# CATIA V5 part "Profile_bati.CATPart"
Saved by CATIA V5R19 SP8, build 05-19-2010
Part number: Profile_bati
Bounding box of the stored display mesh (mm): x -253 to 253, y -52.5 to 72.5, z -226 to 100
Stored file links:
  G:\EU_thinkMotion\CFAO_2010\MMS_groupe1\MMS_groupe1\OK\vduret\vduret\CATIA\Profile_bati.CATPart
  G:\EU_thinkMotion\CFAO_2010\MMS_groupe1\MMS_groupe1\OK\vduret\vduret\CATIA\Axe_outil_g.CATPart
  F:\CFAO TP\Machine_de_coupe.CATProduct
  G:\EU_thinkMotion\CFAO_2010\MMS_groupe1\MMS_groupe1\OK\vduret\vduret\CATIA\Tige_sync.CATPart
  G:\EU_thinkMotion\CFAO_2010\MMS_groupe1\MMS_groupe1\OK\vduret\vduret\CATIA\Axe.CATPart
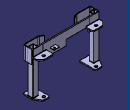
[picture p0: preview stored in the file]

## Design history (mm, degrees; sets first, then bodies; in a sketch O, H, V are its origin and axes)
Parameters
  Largeur_bati = 500 mm
  Hauteur_bati = 70 mm
External parameters (linked from other documents)
  External.Longueur_axe_couronne = 200 mm
Body1 (main body)
  Sketch1 on xy-plane, origin (0, 0, 0), H (1, 0, 0), V (0, 1, 0)
    line L1 (-250, 17.5) -> (-175, 17.5)
    line L2 (-210, 9.5) -> (-210, -17.5)
    line L3 (-210, -17.5) -> (-250, -17.5)
    line L4 (-250, 11.5) -> (-250, 17.5)
    line L5 (-246, 13.5) -> (-214, 13.5)
    line L6 (-214, 13.5) -> (-214, -13.5)
    line L7 (-214, -13.5) -> (-246, -13.5)
    line L8 (-246, -13.5) -> (-246, 13.5)
    line L9 (175, 17.5) -> (250, 17.5)
    line L10 (250, -21.5) -> (210, -21.5)
    line L11 (250, 17.5) -> (250, 11.5)
    line L12 (210, -21.5) -> (210, 9.5)
    line L13 (214, 13.5) -> (246, 13.5)
    line L14 (246, -17.5) -> (214, -17.5)
    line L15 (246, 13.5) -> (246, -17.5)
    line L16 (214, -17.5) -> (214, 13.5)
    point P9 (0, 0)
    line L17 (-175, 17.5) -> (175, 17.5)
    line L18 (210, 9.5) -> (-210, 9.5)
    line L19 (-253, 11.5) -> (-250, 11.5)
    line L20 (-250, -17.5) -> (-250, -48.5)
    line L21 (-253, -38.5) -> (-253, 11.5)
    line L22 (250, 11.5) -> (253, 11.5)
    line L23 (253, 11.5) -> (253, -36.5)
    line L24 (250, -48.5) -> (250, -21.5)
    line L25 (-250, -48.5) -> (-144.0718, -48.5)
    line L26 (-143, -52.5) -> (-253, -52.5)
    line L27 (-253, -52.5) -> (-253, -38.5)
    point P33 (253, -52.5)
    line L28 (253, -52.5) -> (143, -52.5)
    line L29 (144.0718, -48.5) -> (250, -48.5)
    line L30 (253, -36.5) -> (253, -52.5)
    point P35 (144.0718, -48.5)
    line L31 (-144.0718, -48.5) -> (-113.7609, -31)
    line L32 (-143, -52.5) -> (-111.7609, -34.4641)
    point P38 (-111.7609, -34.4641)
    line L33 (144.0718, -48.5) -> (113.7609, -31)
    line L34 (143, -52.5) -> (111.7609, -34.4641)
    line L35 (113.7609, -31) -> (111.7609, -34.4641)
    line L36 (-113.7609, -31) -> (-111.7609, -34.4641)
    point P41 (-111.7609, -34.4641)
    point P42 (-198, -52.5)
    distance L5 L1 = 4
    distance L6 L2 = 4
    distance L7 L3 = 4
    distance L8 L4 = 4
    distance L13 L9 = 4
    distance L15 L11 = 4
    distance L14 L10 = 4
    distance L16 L12 = 4
    distance L4 V = 250 {= Largeur_bati /2}
    distance V L11 = 250 {= Largeur_bati /2}
    distance L1 H = 17.5
    distance L9 H = 17.5
    distance L9 L14 = 35
    distance L17 L18 = 8
    length L19 = 3
    distance L19 L1 = 6
    distance L22 L9 = 6
    length L26 = 110
    length L28 = 110
    length L33 = 35
    length L31 = 35
    angle L34 L28 = 30
    angle L32 L26 = 30
    distance L25 L26 = 4
    distance L31 L32 = 4
    distance L1 L3 = 35
    distance L4 L2 = 40
    distance L33 L34 = 4
    distance L28 L29 = 4
    distance L23 L24 = 3
    distance L12 L11 = 40
    distance L17 L26 = 70 {= Hauteur_bati}
    horizontal: L1 H, L3 H, L5 H, L7 H, L10 H, L9 H, L17 H, L18 H, L19 H, L22 H, L25 H, L26 H, L28 H, L29 H
    vertical: L2 V, L4 V, L6 V, L8 V, L16 V, L12 V, L20 V, L21 V, L23 V, L24 V, L27 V, L30 V
    coincidence: L17 L1, L20 L4, L24 L11, P33 L23, P35 L25, P41 L32, L36 P38
    perpendicularity: L35 L33, L31 L36
    midpoint: P42 L26
  Pad1: profile Sketch1, direction (0, 0, 1), length 100
  Sketch2 on start face of Pad1, origin (0, 0, 0), H (1, 0, 0), V (0, -1, 0)
    line L1 (-250, 17.5) -> (-210, 17.5)
    line L2 (-210, 17.5) -> (-210, -17.5)
    line L3 (-210, -17.5) -> (-250, -17.5)
    line L4 (-250, -17.5) -> (-250, 17.5)
    line L5 (-246, 13.5) -> (-214, 13.5)
    line L6 (-214, 13.5) -> (-214, -13.5)
    line L7 (-214, -13.5) -> (-246, -13.5)
    line L8 (-246, -13.5) -> (-246, 13.5)
    line L9 (210, 21.5) -> (250, 21.5)
    line L10 (250, 21.5) -> (250, -17.5)
    line L11 (250, -17.5) -> (210, -17.5)
    line L12 (210, -17.5) -> (210, 21.5)
    line L13 (214, 17.5) -> (246, 17.5)
    line L14 (246, 17.5) -> (246, -13.5)
    line L15 (246, -13.5) -> (214, -13.5)
    line L16 (214, -13.5) -> (214, 17.5)
    reference projected line E1 (-250, 17.5) -> (-175, 17.5) from edge [start face of Pad1 | face of Pad1 from Sketch1.L3]
    reference projected line E2 (-210, 17.5) -> (-210, -11.5) from edge [start face of Pad1 | face of Pad1 from Sketch1.L2]
    reference projected line E3 (-175, -17.5) -> (-250, -17.5) from edge [start face of Pad1 | face of Pad1 from Sketch1.L1]
    reference projected line E4 (-250, -17.5) -> (-250, -13.5) from edge [start face of Pad1 | face of Pad1 from Sketch1.L4]
    reference projected line E5 (-214, 15.5) -> (-214, -15.5) from edge [face of Pad1 from Sketch1.L6 | start face of Pad1]
    reference projected line E6 (-248, 13.5) -> (-177, 13.5) from edge [face of Pad1 from Sketch1.L7 | start face of Pad1]
    reference projected line E7 (-246, -15.5) -> (-246, 15.5) from edge [face of Pad1 from Sketch1.L8 | start face of Pad1]
    reference projected line E8 (-177, -13.5) -> (-248, -13.5) from edge [face of Pad1 from Sketch1.L5 | start face of Pad1]
    reference projected line E9 (175, 21.5) -> (250, 21.5) from edge [start face of Pad1 | face of Pad1 from Sketch1.L10]
    reference projected line E10 (210, -11.5) -> (210, 19.5) from edge [start face of Pad1 | face of Pad1 from Sketch1.L12]
    reference projected line E11 (250, -13.5) -> (250, -17.5) from edge [start face of Pad1 | face of Pad1 from Sketch1.L11]
    reference projected line E12 (250, -17.5) -> (175, -17.5) from edge [start face of Pad1 | face of Pad1 from Sketch1.L9]
    reference projected line E13 (177, 17.5) -> (248, 17.5) from edge [face of Pad1 from Sketch1.L14 | start face of Pad1]
    reference projected line E14 (246, 17.5) -> (246, -15.5) from edge [face of Pad1 from Sketch1.L15 | start face of Pad1]
    reference projected line E15 (248, -13.5) -> (177, -13.5) from edge [face of Pad1 from Sketch1.L13 | start face of Pad1]
    reference projected line E16 (214, -15.5) -> (214, 17.5) from edge [face of Pad1 from Sketch1.L16 | start face of Pad1]
    horizontal: L1 H, L3 H, L5 H, L7 H, L9 H, L11 H, L13 H, L15 H
    vertical: L2 V, L4 V, L6 V, L8 V, L10 V, L12 V, L14 V, L16 V
    coincidence: L1 E1, L2 E2, L3 E3, L4 E4, L6 E5, L5 E6, L8 E7, L7 E8, L9 E9, L12 E10, L10 E11, L11 E12, L13 E13, L14 E14, L15 E15, L16 E16
  Pad2: profile Sketch2, direction (0, 0, -1), length 220 {= External.Longueur_axe_couronne +20mm}
  Sketch3 on end face of Pad2, origin (0, 0, -220), H (1, 0, 0), V (0, -1, 0)
    line L1 (-253, 52.5) -> (-253, -17.5)
    point P2 (-253, -17.5)
    line L2 (-253, -17.5) -> (-223, -67.5)
    line L3 (-223, -67.5) -> (-173, -67.5)
    line L4 (-173, -67.5) -> (-173, 52.5)
    line L5 (-173, 52.5) -> (-253, 52.5)
    circle A1 centre (-198, -47.5) radius 10
    point P6 (-198, -47.5)
    line L6 (253, 52.5) -> (253, -17.5)
    point P8 (253, -17.5)
    line L7 (253, -17.5) -> (223, -67.5)
    line L8 (223, -67.5) -> (173, -67.5)
    line L9 (173, -67.5) -> (173, 52.5)
    line L10 (173, 52.5) -> (253, 52.5)
    circle A2 centre (198, -47.5) radius 10
    point P12 (198, -47.5)
    reference projected line E1 (-253, 52.5) -> (-143, 52.5) from edge [start face of Pad1 | face of Pad1 from Sketch1.L26]
    reference projected line E2 (-253, -13.5) -> (-253, 36.5) from edge [start face of Pad1 | face of Pad1 from Sketch1.L21]
    reference projected line E3 (143, 52.5) -> (253, 52.5) from edge [start face of Pad1 | face of Pad1 from Sketch1.L28]
    reference projected line E4 (253, 36.5) -> (253, -13.5) from edge [start face of Pad1 | face of Pad1 from Sketch1.L23]
    reference projected line E5 (175, -17.5) -> (250, -17.5) from edge [face of Pad2 | end face of Pad2]
    reference projected line E6 (-250, -17.5) -> (-175, -17.5) from edge [face of Pad2 | end face of Pad2]
    distance P6 L5 = 100 {= Hauteur_bati +30mm}
    radius A1 = 10
    distance P12 L10 = 100 {= Hauteur_bati +30mm}
    radius A2 = 10
    length L5 = 80
    distance P6 L1 = 55
    length L10 = 80
    distance P12 L6 = 55
    length L3 = 50
    length L8 = 50
    distance P6 L3 = 20
    distance P12 L8 = 20
    vertical: L1 V, L4 V, L6 V, L9 V
    horizontal: L3 H, L5 H, L8 H, L10 H
    coincidence: L5 E1, L1 E2, L10 E3, L6 E4, P8 E5, P2 E6
  Pad3: profile Sketch3, direction (0, 0, -1), length 6, opposite side length 2
  Plane1: type Offset, RefPlane xy-plane, Offset 42
  Sketch4 on Plane1, origin (0, 0, 42), H (1, 0, 0), V (0, 1, 0)
    line L1 (-250, 45.5) -> (-250, 17.5)
    line L2 (-250, 17.5) -> (-150, 17.5)
    line L3 (-150, 17.5) -> (-150, 72.5)
    line L4 (-150, 72.5) -> (-222, 72.5)
    point P5 (-222, 72.5)
    line L5 (-222, 72.5) -> (-250, 45.5)
    line L6 (150, 17.5) -> (150, 72.5)
    line L7 (150, 72.5) -> (222, 72.5)
    point P8 (222, 72.5)
    line L8 (222, 72.5) -> (250, 45.5)
    line L9 (250, 45.5) -> (250, 17.5)
    line L10 (250, 17.5) -> (150, 17.5)
    reference projected line E1 (-250, 17.5) -> (-250, 13.5) from edge [face of Pad2 | end face of Pad1]
    reference projected line E2 (-175, 17.5) -> (-250, 17.5) from edge [face of Pad2 | end face of Pad1]
    circle A1 centre (-198, 47.5) radius 10
    point P11 (-198, 47.5)
    reference projected line E3 (-253, 13.5) -> (-253, -36.5) from edge [face of Pad1 from Sketch1.L21 | end face of Pad1]
    reference projected line E4 (-253, -52.5) -> (-143, -52.5) from edge [face of Pad1 from Sketch1.L26 | end face of Pad1]
    reference projected line E5 (250, 13.5) -> (250, 17.5) from edge [face of Pad2 | end face of Pad1]
    reference projected line E6 (250, 17.5) -> (175, 17.5) from edge [face of Pad2 | end face of Pad1]
    circle A2 centre (198, 47.5) radius 10
    point P12 (198, 47.5)
    reference projected line E7 (253, -36.5) -> (253, 13.5) from edge [face of Pad1 from Sketch1.L23 | end face of Pad1]
    reference projected line E8 (143, -52.5) -> (253, -52.5) from edge [face of Pad1 from Sketch1.L28 | end face of Pad1]
    length L2 = 100
    distance P5 L1 = 28
    radius A1 = 10
    distance P11 E3 = 55
    distance P11 E4 = 100 {= Hauteur_bati +30mm}
    length L1 = 28
    distance L6 L9 = 100
    radius A2 = 10
    distance P12 E7 = 55
    distance P12 E8 = 100 {= Hauteur_bati +30mm}
    length L9 = 28
    distance P8 L9 = 28
    distance P11 L4 = 25
    distance P12 L7 = 25
    vertical: L1 V, L3 V, L6 V, L9 V
    horizontal: L2 H, L4 H, L7 H, L10 H
    coincidence: L1 E1, L2 E2, L9 E5, L10 E6
  Pad4: profile Sketch4, direction (0, 0, 1), length 8
  Sketch5 on face of Pad1 from Sketch1.L17, origin (0, 17.5, 0), H (-1, 0, 0), V (0, 0, 1)
    line L1 (0, 42) -> (175, 42)
    line L2 (175, 42) -> (175, 0)
    line L3 (175, 0) -> (0, 0)
    line L4 (0, 0) -> (0, 42)
    reference projected line E1 (150, 42) -> (222, 42) from edge [start face of Pad4 | face of Pad4 from Sketch4.L4]
    reference projected line E2 (175, 0) -> (175, 100) from edge [face of Pad2 | face of Pad1 from Sketch1.L17]
    reference projected line E3 (-175, 0) -> (175, 0) from edge [start face of Pad1 | face of Pad1 from Sketch1.L17]
    horizontal: L1 H, L3 H
    vertical: L2 V, L4 V
    coincidence: L4 V, L1 E1, L2 E2, L3 E3
  Pocket1: profile Sketch5, direction (0, -1, 0), through (limit type 6)
  Plane2: type Offset, RefPlane Plane1, Offset -4, reversed
  Sketch6 on Plane2, origin (0, 0, 46), H (1, 0, 0), V (0, 1, 0)
    line L1 (80, 47.5) -> (120, 47.5)
    line L2 (120, 47.5) -> (120, 17.5)
    line L3 (120, 17.5) -> (80, 17.5)
    line L4 (80, 17.5) -> (80, 47.5)
    reference projected line E1 (175, 17.5) -> (-175, 17.5) from edge [face of Pad1 from Sketch1.L17 | end face of Pad1]
    reference projected line E2 (150, 72.5) -> (150, 17.5) from edge [face of Pad4 from Sketch4.L6 | end face of Pad4]
    circle A1 centre (105, 35.5) radius 7
    point P5 (105, 35.5)
    distance L2 E2 = 30
    radius A1 = 7
    distance P5 L3 = 18
    length L4 = 30
    distance P5 L2 = 15
    length L3 = 40
    horizontal: L1 H, L3 H
    vertical: L2 V, L4 V
    coincidence: L3 E1
  Pad5: profile Sketch6, direction (0, 0, 1), length 3
  Fillet1: radius 20, on edge [face of Pad1 from Sketch1.L32 | face of Pad1 from Sketch1.L26]
  Fillet2: radius 20, on edge [face of Pad1 from Sketch1.L25 | face of Pad1 from Sketch1.L31]
  Fillet3: radius 20, on edge [face of Pad1 from Sketch1.L28 | face of Pad1 from Sketch1.L34]
  Fillet4: radius 20, on edge [face of Pad1 from Sketch1.L33 | face of Pad1 from Sketch1.L29]
  Fillet5: radius 5, on edge [face of Pad1 from Sketch1.L26 | face of Pad1 from Sketch1.L27]
  Fillet6: radius 5, on edge [face of Pad1 from Sketch1.L20 | face of Pad1 from Sketch1.L25]
  Fillet7: radius 5, on edge [face of Pad1 from Sketch1.L29 | face of Pad1 from Sketch1.L24]
  Fillet8: radius 5, on edge [face of Pad1 from Sketch1.L30 | face of Pad1 from Sketch1.L28]
  Fillet9: radius 2, on edge [face of Pad4 | face of Pad2]
  Fillet10: radius 2, on edge [face of Pad4 | face of Pad2]
  Fillet11: radius 2, on edge [face of Pad4 | face of Pad2]
  Fillet12: radius 2, on edge [face of Pad2 | face of Pad2] (x4)
  Fillet13: radius 2, on edge [face of Pad2 | face of Pad2]
  Fillet14: radius 2, on edge [face of Pad2 | face of Pad4]
  Fillet15: radius 2, on edge [face of Pad2 | face of Pad4]
  Fillet16: radius 2, on edge [face of Pad2 | face of Pad4]
  Fillet17: radius 2, on edge [face of Pad2 | face of Pad2] (x4)
  Fillet18: radius 2, on edge [face of Pad2 | face of Pad2]
  Fillet19: radius 2, on edge [face of Pad2 | start face of Pad3]; edge [start face of Pad3 | face of Pad4]
  Fillet20: radius 2, on edge [face of Pocket1 | face of Pad2]; edge [face of Pad2 | end face of Pad4]
  Fillet21: radius 2, on edge [face of Pad2 | end face of Pad4]; edge [face of Pad1 from Sketch1.L17 | end face of Pad4]; edge [start face of Pad4 | face of Pad2]
  Fillet22: radius 2, on edge [face of Pad2 | start face of Pad3]; edge [face of Pad4 | start face of Pad3]
  Fillet23: radius 10, on edge [face of Pad3 from Sketch3.L2 | face of Pad3 from Sketch3.L1]
  Fillet24: radius 10, on edge [face of Pad3 from Sketch3.L6 | face of Pad3 from Sketch3.L7]
  Fillet25: radius 10, on edge [face of Pad3 from Sketch3.L7 | face of Pad3 from Sketch3.L8]
  Fillet26: radius 10, on edge [face of Pad3 from Sketch3.L8 | face of Pad3 from Sketch3.L9]
  Fillet27: radius 10, on edge [face of Pad3 from Sketch3.L3 | face of Pad3 from Sketch3.L2]
  Fillet28: radius 10, on edge [face of Pad3 from Sketch3.L4 | face of Pad3 from Sketch3.L3]
  Fillet29: radius 10, on edge [face of Pad4 | face of Pad4 from Sketch4.L5]; edge [face of Pad4 from Sketch4.L5 | face of Pad4 from Sketch4.L4]; edge [face of Pad4 from Sketch4.L4 | face of Pad4 from Sketch4.L3]; edge [face of Pad4 from Sketch4.L8 | face of Pad4]; edge [face of Pad4 from Sketch4.L7 | face of Pad4 from Sketch4.L8]; edge [face of Pad4 from Sketch4.L6 | face of Pad4 from Sketch4.L7]
Relations
  Sketch3.distance(P6 L5) = Hauteur_axe_bras Hauteur_axe_bras (deactivated)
